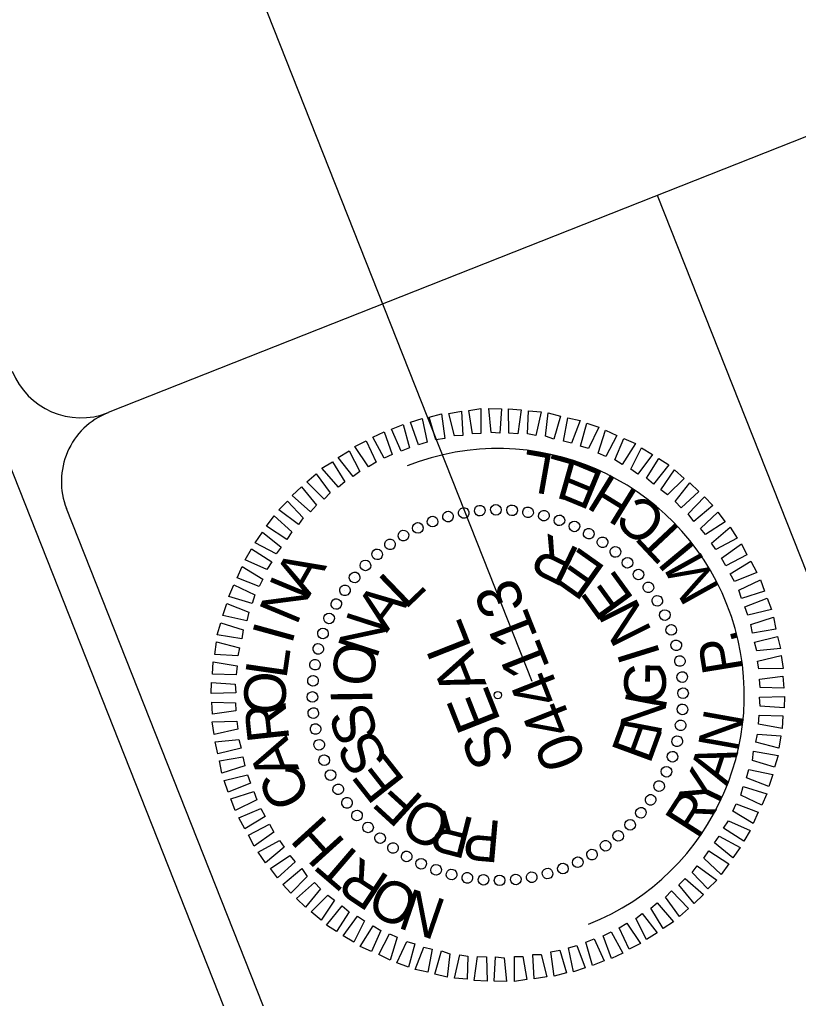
# Model space of a CAD drawing. Extents: x 1247235 to 1260080, y 742320 to 754020.
# Drawn here: x 1251273 to 1251748, y 750320 to 750916 of the extents above; entities that cross this region are included whole.
import ezdxf

# ---------------------------------------------------------------- set-up
doc = ezdxf.new("R2010")
doc.units = 0
for name, color, linetype in [('Scratch_Level_0', 7, 'Continuous'), ('Scratch_Level_1', 7, 'Continuous'), ('Sheet Professional Seal CELL', 7, 'Continuous'), ('Sheet Title CELL', 7, 'Continuous')]:
    doc.layers.add(name, color=color, linetype=linetype)

msp = doc.modelspace()

# ---------------------------------------------------------------- linework, layer by layer
at = {"layer": 'Scratch_Level_0'}
msp.add_circle((1251564.66, 750504.87), 2.25, dxfattribs=at)
msp.add_arc((1251564.66, 750504.87), 150.14, 291.57435, 111.57435, dxfattribs=at)
at = {"layer": 'Scratch_Level_1'}
msp.add_line((1251585.67, 750513.04), (1251023.82, 751933.97), dxfattribs=at)
at = {"layer": 'Sheet Professional Seal CELL'}
for p, q in [((1251544.04, 750615.76), (1251544.04, 750615.76)), ((1251553.57, 750617.35), (1251553.57, 750617.35)), ((1251563.52, 750617.9), (1251563.52, 750617.9)), ((1251573.38, 750617.44), (1251573.38, 750617.44)), ((1251583.19, 750616.48), (1251583.19, 750616.48)), ((1251592.79, 750614.23), (1251592.79, 750614.23)), ((1251525.01, 750610.65), (1251525.01, 750610.65)), ((1251534.46, 750613.67), (1251534.46, 750613.67)), ((1251602.35, 750611.48), (1251602.35, 750611.48)), ((1251515.88, 750606.81), (1251515.88, 750606.81)), ((1251611.32, 750607.76), (1251611.32, 750607.76)), ((1251620.32, 750603.34), (1251620.32, 750603.34)), ((1251498.84, 750596.68), (1251498.84, 750596.68)), ((1251507.38, 750601.99), (1251507.38, 750601.99)), ((1251628.45, 750598.09), (1251628.45, 750598.09)), ((1251491.04, 750590.69), (1251491.04, 750590.69)), ((1251636.41, 750592.04), (1251636.41, 750592.04)), ((1251643.82, 750585.53), (1251643.82, 750585.53)), ((1251484, 750584.04), (1251484, 750584.04)), ((1251650.48, 750578.49), (1251650.48, 750578.49)), ((1251477.49, 750576.62), (1251477.49, 750576.62)), ((1251471.44, 750568.67), (1251471.44, 750568.67)), ((1251656.46, 750570.69), (1251656.46, 750570.69)), ((1251466.19, 750560.54), (1251466.19, 750560.54)), ((1251661.78, 750562.15), (1251661.78, 750562.15)), ((1251461.77, 750551.53), (1251461.77, 750551.53)), ((1251666.59, 750553.65), (1251666.59, 750553.65)), ((1251458.05, 750542.57), (1251458.05, 750542.57)), ((1251670.44, 750544.52), (1251670.44, 750544.52)), ((1251455.3, 750533.01), (1251455.3, 750533.01)), ((1251673.45, 750535.07), (1251673.45, 750535.07)), ((1251675.54, 750525.49), (1251675.54, 750525.49)), ((1251453.05, 750523.41), (1251453.05, 750523.41)), ((1251452.09, 750513.59), (1251452.09, 750513.59)), ((1251677.14, 750515.96), (1251677.14, 750515.96)), ((1251451.63, 750503.73), (1251451.63, 750503.73)), ((1251564.66, 750504.87), (1251564.66, 750504.87)), ((1251677.68, 750506.01), (1251677.68, 750506.01)), ((1251677.22, 750496.15), (1251677.22, 750496.15)), ((1251452.18, 750493.79), (1251452.18, 750493.79)), ((1251453.77, 750484.25), (1251453.77, 750484.25)), ((1251676.27, 750486.34), (1251676.27, 750486.34)), ((1251455.86, 750474.68), (1251455.86, 750474.68)), ((1251674.01, 750476.74), (1251674.01, 750476.74)), ((1251458.87, 750465.22), (1251458.87, 750465.22)), ((1251671.26, 750467.18), (1251671.26, 750467.18)), ((1251462.72, 750456.1), (1251462.72, 750456.1)), ((1251667.55, 750458.21), (1251667.55, 750458.21)), ((1251467.54, 750447.6), (1251467.54, 750447.6)), ((1251663.12, 750449.21), (1251663.12, 750449.21)), ((1251472.85, 750439.05), (1251472.85, 750439.05)), ((1251657.87, 750441.08), (1251657.87, 750441.08)), ((1251478.84, 750431.26), (1251478.84, 750431.26)), ((1251651.82, 750433.12), (1251651.82, 750433.12)), ((1251485.49, 750424.21), (1251485.49, 750424.21)), ((1251645.32, 750425.71), (1251645.32, 750425.71)), ((1251492.91, 750417.71), (1251492.91, 750417.71)), ((1251638.27, 750419.05), (1251638.27, 750419.05)), ((1251500.86, 750411.66), (1251500.86, 750411.66)), ((1251630.47, 750413.07), (1251630.47, 750413.07)), ((1251508.99, 750406.41), (1251508.99, 750406.41)), ((1251621.93, 750407.75), (1251621.93, 750407.75)), ((1251518, 750401.98), (1251518, 750401.98)), ((1251613.43, 750402.94), (1251613.43, 750402.94)), ((1251526.96, 750398.27), (1251526.96, 750398.27)), ((1251536.52, 750395.52), (1251536.52, 750395.52)), ((1251585.27, 750393.99), (1251585.27, 750393.99)), ((1251594.85, 750396.08), (1251594.85, 750396.08)), ((1251604.31, 750399.09), (1251604.31, 750399.09)), ((1251546.12, 750393.26), (1251546.12, 750393.26)), ((1251555.94, 750392.31), (1251555.94, 750392.31)), ((1251565.8, 750391.85), (1251565.8, 750391.85)), ((1251575.74, 750392.39), (1251575.74, 750392.39))]:
    msp.add_line(p, q, dxfattribs=at)
for points in [[(1251526.92, 750660.28), (1251522.88, 750674.17), (1251530.32, 750676.15), (1251532.35, 750661.22)], [(1251538.25, 750662.83), (1251534.79, 750676.46), (1251542.49, 750677.81), (1251543.31, 750662.89)], [(1251549.37, 750664.08), (1251546.96, 750678.13), (1251554.44, 750679.39), (1251554.42, 750664.14)], [(1251560.65, 750664.91), (1251559.29, 750679.38), (1251566.85, 750679.22), (1251565.96, 750664.35)], [(1251571.51, 750664.37), (1251571.2, 750679.24), (1251578.92, 750678.67), (1251576.94, 750664.1)], [(1251582.79, 750663.99), (1251583.31, 750677.98), (1251591.04, 750677.41), (1251587.76, 750663.05)], [(1251593.78, 750662.53), (1251595.42, 750676.73), (1251602.93, 750674.86), (1251598.87, 750660.67)], [(1251604.63, 750659.56), (1251607.27, 750673.67), (1251614.91, 750672.09), (1251609.68, 750658.41)], [(1251505.91, 750653.43), (1251499.91, 750666.78), (1251507.02, 750669.6), (1251510.94, 750655.42)], [(1251516.46, 750657.36), (1251511.5, 750671.12), (1251518.57, 750673.44), (1251521.65, 750658.93)], [(1251615.06, 750656.42), (1251618.92, 750670.53), (1251626.18, 750668.08), (1251619.99, 750654.98)], [(1251495.54, 750649.09), (1251488.48, 750662.02), (1251495.43, 750665.26), (1251500.39, 750651.49)], [(1251625.91, 750652.25), (1251630.27, 750666.31), (1251637.15, 750662.98), (1251630.58, 750650.22)], [(1251485.99, 750643.86), (1251477.68, 750656.3), (1251484.55, 750659.74), (1251490.68, 750646.68)], [(1251635.96, 750648.24), (1251641.53, 750661.08), (1251648.53, 750658.05), (1251640.46, 750645.42)], [(1251476.69, 750638), (1251467.5, 750649.61), (1251474.12, 750653.68), (1251480.59, 750641)], [(1251645.76, 750642.43), (1251652.24, 750655.4), (1251658.87, 750651.49), (1251650.05, 750639.53)], [(1251467.64, 750631.52), (1251457.53, 750643.01), (1251463.94, 750647), (1251471.45, 750634.72)], [(1251655.18, 750636.96), (1251662.79, 750648.92), (1251668.91, 750645.06), (1251659.51, 750633.35)], [(1251458.92, 750624.2), (1251448.43, 750634.82), (1251454.01, 750639.68), (1251462.49, 750628.03)], [(1251664.05, 750629.82), (1251672.29, 750642.03), (1251678.2, 750636.87), (1251668.13, 750626.84)], [(1251672.63, 750622.81), (1251681.7, 750634.14), (1251687.19, 750628.81), (1251676.33, 750618.95)], [(1251450.58, 750616.55), (1251439.42, 750626.41), (1251445.04, 750631.78), (1251454.35, 750620.46)], [(1251443.23, 750608.81), (1251431.28, 750617.63), (1251436.69, 750622.91), (1251446.22, 750612.89)], [(1251680.66, 750615.34), (1251690.65, 750625.58), (1251695.64, 750620.3), (1251683.99, 750610.61)], [(1251436.18, 750599.73), (1251423.84, 750607.67), (1251428.55, 750614.13), (1251439.2, 750604.31)], [(1251688.06, 750606.42), (1251698.72, 750616.19), (1251703.16, 750610.45), (1251691.27, 750602.6)], [(1251429.75, 750590.89), (1251416.91, 750597.67), (1251421.4, 750604.05), (1251432.73, 750594.98)], [(1251694.76, 750597.45), (1251706.2, 750607.05), (1251710.48, 750600.52), (1251697.54, 750593.47)], [(1251701.03, 750588.31), (1251713.1, 750596.96), (1251716.45, 750590.3), (1251703.64, 750583.54)], [(1251424.07, 750581.39), (1251410.85, 750587.29), (1251414.76, 750593.92), (1251427.1, 750585.97)], [(1251706.26, 750578.77), (1251718.74, 750586.36), (1251722.39, 750579.58), (1251708.87, 750573.99)], [(1251419.43, 750571.09), (1251406.04, 750576.2), (1251409.08, 750583.2), (1251421.54, 750575.55)], [(1251711.44, 750568.72), (1251724.62, 750575.14), (1251727.15, 750568.16), (1251713.21, 750563.61)], [(1251415.09, 750560.66), (1251400.82, 750564.94), (1251403.85, 750571.94), (1251416.66, 750565.88)], [(1251411.75, 750550.14), (1251397.18, 750553.34), (1251399.63, 750560.6), (1251413.1, 750555.28)], [(1251715.2, 750558.59), (1251728.8, 750563.97), (1251731.32, 750556.98), (1251716.98, 750553.49)], [(1251408.86, 750539.08), (1251393.83, 750541.61), (1251396.07, 750548.79), (1251409.55, 750544.68)], [(1251718.71, 750547.88), (1251732.64, 750552.42), (1251734.12, 750545.02), (1251719.86, 750542.53)], [(1251406.44, 750528.69), (1251392.28, 750529.62), (1251393.35, 750537.31), (1251407.38, 750533.66)], [(1251721.01, 750537.18), (1251735.14, 750540.59), (1251736.83, 750533.27), (1251722.36, 750531.91)], [(1251405.43, 750517.16), (1251391.02, 750517.51), (1251391.38, 750525.16), (1251405.91, 750522.67)], [(1251722.92, 750525.6), (1251737.35, 750528.88), (1251738.49, 750521.11), (1251723.62, 750520.79)], [(1251724.18, 750514.48), (1251738.39, 750516.47), (1251738.86, 750509.15), (1251724.45, 750509.5)], [(1251405.18, 750506.17), (1251390.1, 750505.77), (1251390.29, 750512.63), (1251404.74, 750511.57)], [(1251724.13, 750503.57), (1251739.22, 750503.97), (1251739.02, 750497.12), (1251724.57, 750498.18)], [(1251405.14, 750495.27), (1251390.92, 750493.28), (1251390.45, 750500.59), (1251404.86, 750500.24)], [(1251406.39, 750484.15), (1251391.96, 750480.86), (1251390.82, 750488.64), (1251405.7, 750488.96)], [(1251723.88, 750492.59), (1251738.29, 750492.24), (1251737.93, 750484.59), (1251723.4, 750487.07)], [(1251408.31, 750472.57), (1251394.17, 750469.16), (1251392.49, 750476.48), (1251406.95, 750477.84)], [(1251722.87, 750481.06), (1251737.03, 750480.12), (1251735.96, 750472.44), (1251721.93, 750476.09)], [(1251410.6, 750461.86), (1251396.67, 750457.32), (1251395.2, 750464.72), (1251409.45, 750467.22)], [(1251720.45, 750470.66), (1251735.48, 750468.14), (1251733.24, 750460.96), (1251719.76, 750465.07)], [(1251717.57, 750459.6), (1251732.13, 750456.41), (1251729.68, 750449.15), (1251716.21, 750454.47)], [(1251414.11, 750451.15), (1251400.51, 750445.78), (1251397.99, 750452.76), (1251412.34, 750456.26)], [(1251714.22, 750449.09), (1251728.5, 750444.81), (1251725.46, 750437.8), (1251712.66, 750443.87)], [(1251417.87, 750441.03), (1251404.69, 750434.6), (1251402.17, 750441.59), (1251416.1, 750446.13)], [(1251423.06, 750430.98), (1251410.58, 750423.38), (1251406.93, 750430.17), (1251420.44, 750435.75)], [(1251709.88, 750438.66), (1251723.27, 750433.55), (1251720.23, 750426.54), (1251707.77, 750434.2)], [(1251428.28, 750421.43), (1251416.22, 750412.79), (1251412.86, 750419.45), (1251425.67, 750426.21)], [(1251705.24, 750428.36), (1251718.46, 750422.46), (1251714.55, 750415.83), (1251702.21, 750423.77)], [(1251699.56, 750418.85), (1251712.41, 750412.08), (1251707.91, 750405.7), (1251696.58, 750414.77)], [(1251434.56, 750412.3), (1251423.11, 750402.69), (1251418.83, 750409.23), (1251431.77, 750416.28)], [(1251441.25, 750403.33), (1251430.6, 750393.55), (1251426.15, 750399.3), (1251438.05, 750407.15)], [(1251693.14, 750410.02), (1251705.47, 750402.08), (1251700.77, 750395.62), (1251690.11, 750405.44)], [(1251686.08, 750400.94), (1251698.04, 750392.12), (1251692.63, 750386.83), (1251683.1, 750396.86)], [(1251448.65, 750394.4), (1251438.67, 750384.16), (1251433.67, 750389.45), (1251445.33, 750399.14)], [(1251456.68, 750386.93), (1251447.61, 750375.6), (1251442.12, 750380.93), (1251452.98, 750390.79)], [(1251678.74, 750393.2), (1251689.9, 750383.34), (1251684.28, 750377.97), (1251674.96, 750389.29)], [(1251465.26, 750379.92), (1251457.03, 750367.71), (1251451.11, 750372.88), (1251461.18, 750382.9)], [(1251670.39, 750385.54), (1251680.88, 750374.93), (1251675.3, 750370.06), (1251666.83, 750381.71)], [(1251474.13, 750372.78), (1251466.53, 750360.82), (1251460.4, 750364.69), (1251469.8, 750376.39)], [(1251661.67, 750378.22), (1251671.78, 750366.74), (1251665.37, 750362.75), (1251657.86, 750375.02)], [(1251483.56, 750367.31), (1251477.07, 750354.35), (1251470.44, 750358.26), (1251479.26, 750370.21)], [(1251652.62, 750371.74), (1251661.81, 750360.13), (1251655.19, 750356.06), (1251648.73, 750368.75)], [(1251493.35, 750361.51), (1251487.79, 750348.66), (1251480.78, 750351.7), (1251488.85, 750364.33)], [(1251643.32, 750365.89), (1251651.63, 750353.45), (1251644.77, 750350.01), (1251638.63, 750363.07)], [(1251503.41, 750357.5), (1251499.05, 750343.44), (1251492.17, 750346.77), (1251498.73, 750359.53)], [(1251633.78, 750360.66), (1251640.83, 750347.72), (1251633.88, 750344.49), (1251628.92, 750358.26)], [(1251514.25, 750353.32), (1251510.39, 750339.21), (1251503.13, 750341.67), (1251509.33, 750354.76)], [(1251612.85, 750352.39), (1251617.81, 750338.62), (1251610.74, 750336.31), (1251607.67, 750350.82)], [(1251623.4, 750356.32), (1251629.4, 750342.96), (1251622.29, 750340.15), (1251618.38, 750354.33)], [(1251524.68, 750350.19), (1251522.04, 750336.08), (1251514.4, 750337.65), (1251519.63, 750351.34)], [(1251535.54, 750347.22), (1251533.89, 750333.02), (1251526.38, 750334.89), (1251530.45, 750349.08)], [(1251546.52, 750345.76), (1251546, 750331.76), (1251538.28, 750332.34), (1251541.55, 750346.7)], [(1251591.06, 750346.92), (1251594.52, 750333.28), (1251586.83, 750331.93), (1251586.01, 750346.85)], [(1251602.4, 750349.46), (1251606.44, 750335.58), (1251598.99, 750333.6), (1251596.96, 750348.52)], [(1251557.8, 750345.38), (1251558.12, 750330.5), (1251550.39, 750331.08), (1251552.37, 750345.65)], [(1251568.66, 750344.83), (1251570.02, 750330.37), (1251562.46, 750330.53), (1251563.36, 750345.4)], [(1251579.94, 750345.67), (1251582.35, 750331.62), (1251574.87, 750330.35), (1251574.89, 750345.6)]]:
    msp.add_lwpolyline(points, close=True, dxfattribs=at)
for centre, major_axis in [((1251553.69, 750617.2), (-0.31, 3.22)), ((1251563.53, 750617.73), (-0.03, 3.24)), ((1251573.37, 750617.4), (0.25, 3.23)), ((1251524.99, 750610.53), (-1.14, 3.03)), ((1251534.35, 750613.59), (-0.87, 3.12)), ((1251543.95, 750615.82), (-0.59, 3.18)), ((1251583.14, 750616.21), (0.53, 3.2)), ((1251592.77, 750614.17), (0.81, 3.14)), ((1251602.19, 750611.31), (1.08, 3.06)), ((1251515.94, 750606.68), (-1.4, 2.92)), ((1251611.33, 750607.63), (1.34, 2.95)), ((1251507.25, 750602.04), (-1.65, 2.79)), ((1251620.1, 750603.17), (1.59, 2.82)), ((1251499, 750596.67), (-1.88, 2.64)), ((1251628.46, 750597.97), (1.83, 2.67)), ((1251491.25, 750590.6), (-2.11, 2.46)), ((1251636.33, 750592.05), (2.06, 2.5)), ((1251484.06, 750583.87), (-2.31, 2.27)), ((1251643.66, 750585.47), (2.27, 2.31)), ((1251477.48, 750576.55), (-2.5, 2.06)), ((1251650.38, 750578.28), (2.46, 2.11)), ((1251471.56, 750568.68), (-2.67, 1.83)), ((1251656.45, 750570.53), (2.64, 1.88)), ((1251466.36, 750560.32), (-2.82, 1.59)), ((1251661.83, 750562.28), (2.79, 1.65)), ((1251461.9, 750551.54), (-2.95, 1.34)), ((1251666.46, 750553.59), (2.92, 1.4)), ((1251458.22, 750542.41), (-3.06, 1.08)), ((1251670.32, 750544.53), (3.03, 1.14)), ((1251455.35, 750532.99), (-3.14, 0.81)), ((1251673.37, 750535.17), (3.12, 0.87)), ((1251453.32, 750523.36), (-3.2, 0.53)), ((1251675.6, 750525.58), (3.18, 0.59)), ((1251676.98, 750515.84), (3.22, 0.31)), ((1251452.13, 750513.58), (-3.23, 0.25)), ((1251451.8, 750503.74), (-3.24, -0.03)), ((1251677.51, 750506), (3.24, 0.03)), ((1251452.33, 750493.91), (-3.22, -0.31)), ((1251677.18, 750496.16), (3.23, -0.25)), ((1251675.99, 750486.39), (3.2, -0.53)), ((1251453.71, 750484.16), (-3.18, -0.59)), ((1251455.94, 750474.57), (-3.12, -0.87)), ((1251673.96, 750476.76), (3.14, -0.81)), ((1251671.09, 750467.34), (3.06, -1.08)), ((1251458.99, 750465.21), (-3.03, -1.14)), ((1251462.85, 750456.15), (-2.92, -1.4)), ((1251667.42, 750458.2), (2.95, -1.34)), ((1251662.96, 750449.43), (2.82, -1.59)), ((1251467.49, 750447.47), (-2.79, -1.65)), ((1251472.86, 750439.22), (-2.64, -1.88)), ((1251657.75, 750441.07), (2.67, -1.83)), ((1251651.83, 750433.2), (2.5, -2.06)), ((1251478.93, 750431.47), (-2.46, -2.11)), ((1251645.26, 750425.87), (2.31, -2.27)), ((1251485.66, 750424.27), (-2.27, -2.31)), ((1251492.98, 750417.69), (-2.06, -2.5)), ((1251638.06, 750419.15), (2.11, -2.46)), ((1251500.85, 750411.78), (-1.83, -2.67)), ((1251622.06, 750407.7), (1.65, -2.79)), ((1251630.31, 750413.08), (1.88, -2.64)), ((1251509.21, 750406.57), (-1.59, -2.82)), ((1251517.99, 750402.11), (-1.34, -2.95)), ((1251613.38, 750403.07), (1.4, -2.92)), ((1251527.12, 750398.44), (-1.08, -3.06)), ((1251594.96, 750396.16), (0.87, -3.12)), ((1251604.32, 750399.21), (1.14, -3.03)), ((1251536.54, 750395.57), (-0.81, -3.14)), ((1251546.17, 750393.54), (-0.53, -3.2)), ((1251555.95, 750392.35), (-0.25, -3.23)), ((1251565.79, 750392.02), (0.03, -3.24)), ((1251575.62, 750392.55), (0.31, -3.22)), ((1251585.37, 750393.93), (0.59, -3.18))]:
    msp.add_ellipse(centre, major_axis=major_axis, ratio=0.999708, dxfattribs=at)
at = {"layer": 'Sheet Title CELL'}
for p, q in [((1253340.81, 745401.2), (1250991.15, 751343.52)), ((1251996.89, 750941.65), (1251327.33, 750676.9)), ((1252025.66, 749889.55), (1251662.01, 750809.23)), ((1251632.59, 749782.52), (1251302.03, 750618.51))]:
    msp.add_line(p, q, dxfattribs=at)
for centre, start, end in [((1251310.78, 750718.75), 201.57435, 291.57435), ((1251343.87, 750635.05), 111.57435, 201.57435)]:
    msp.add_arc(centre, 45, start, end, dxfattribs=at)

# ---------------------------------------------------------------- texts
at = {"layer": 'Sheet Professional Seal CELL'}
for s, height, rotation, p in [('L', 24.75, 169.99374, (1251599.68, 750651.15)), ('L', 24.75, 164.18354, (1251614.31, 750646.85)), ('E', 24.75, 157.60056, (1251630.26, 750640.22)), ('H', 24.75, 148.35576, (1251651.15, 750627.93)), ('C', 24.75, 139.48305, (1251669.1, 750613.11)), ('T', 24.75, 133.18628, (1251680.34, 750601.01)), ('R', 25.37, 154.05576, (1251615.6, 750593.25)), ('I', 24.75, 129.66582, (1251686.02, 750593.72)), ('E', 25.37, 144.69844, (1251631.31, 750582.28)), ('M', 24.75, 118.98993, (1251700.38, 750569.7)), ('A', 25.37, 60.1915, (1251449.61, 750563.91)), ('L', 25.38, 43.9752, (1251508.25, 750556.36)), ('E', 25.37, 125.98611, (1251648.24, 750563.33)), ('N', 25.37, 67.39326, (1251442.15, 750546.68)), ('044113', 26.992, 111.57435, (1251618.88, 750465.75)), ('A', 25.38, 53.33462, (1251497.04, 750542.49)), ('N', 25.37, 116.63074, (1251658.94, 750543.61)), ('N', 25.37, 72.05096, (1251490.87, 750526.27)), ('SEAL', 26.992, 111.57435, (1251575.66, 750466.65)), ('I', 25.37, 74.59449, (1251439.22, 750535.12)), ('.', 24.75, 105.80966, (1251711.59, 750537.05)), ('P', 24.75, 99.22667, (1251714.31, 750519.99)), ('L', 25.37, 81.79522, (1251435.88, 750514.2)), ('O', 25.37, 81.40783, (1251488.04, 750508.94)), ('I', 25.37, 107.27555, (1251663.86, 750529.34)), ('G', 25.37, 88.56459, (1251666.75, 750498.79)), ('O', 25.37, 88.99551, (1251435.42, 750492.73)), ('I', 25.37, 90.76395, (1251488.42, 750499.41)), ('N', 25.37, 79.20831, (1251663.62, 750479.16)), ('R', 25.37, 96.19545, (1251437.82, 750477.47)), ('S', 25.37, 109.47475, (1251492.61, 750480.26)), ('E', 25.37, 69.85124, (1251657.28, 750462.14)), ('N', 24.75, 79.84981, (1251710.84, 750469.48)), ('A', 25.37, 110.59467, (1251443.94, 750459.56)), ('S', 25.37, 118.82996, (1251498.78, 750465.27)), ('E', 25.37, 128.18542, (1251508.88, 750452.57)), ('A', 24.75, 71.66401, (1251704.32, 750449.03)), ('C', 25.37, 117.79422, (1251451.73, 750443.53)), ('Y', 24.75, 64.33686, (1251696.05, 750431.67)), ('F', 25.37, 137.54138, (1251520.45, 750441.67)), ('R', 24.75, 57.41042, (1251686.27, 750416.36)), ('O', 25.37, 156.25559, (1251538.26, 750432.74)), ('R', 25.38, 165.614, (1251551.41, 750429.47)), ('H', 25.37, 132.19383, (1251472.67, 750415.03)), ('P', 25.38, 174.97324, (1251567.44, 750428.07)), ('T', 25.37, 139.39412, (1251484.96, 750404.16)), ('R', 25.37, 146.59486, (1251499.79, 750393.57)), ('O', 25.37, 153.79609, (1251518.47, 750384.27)), ('N', 25.37, 160.99785, (1251534.41, 750379.44))]:
    msp.add_text(s, height=height, rotation=rotation, dxfattribs=at).set_placement(p)

doc.saveas('drawing.dxf')
